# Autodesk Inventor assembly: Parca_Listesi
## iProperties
Created: 2006-07
Part Number: Parca_Listesi
Document SubType Name: Assembly
Designer: rollin42
Part Number: Lubricant Oil
Material: Default
Author: rollin42
